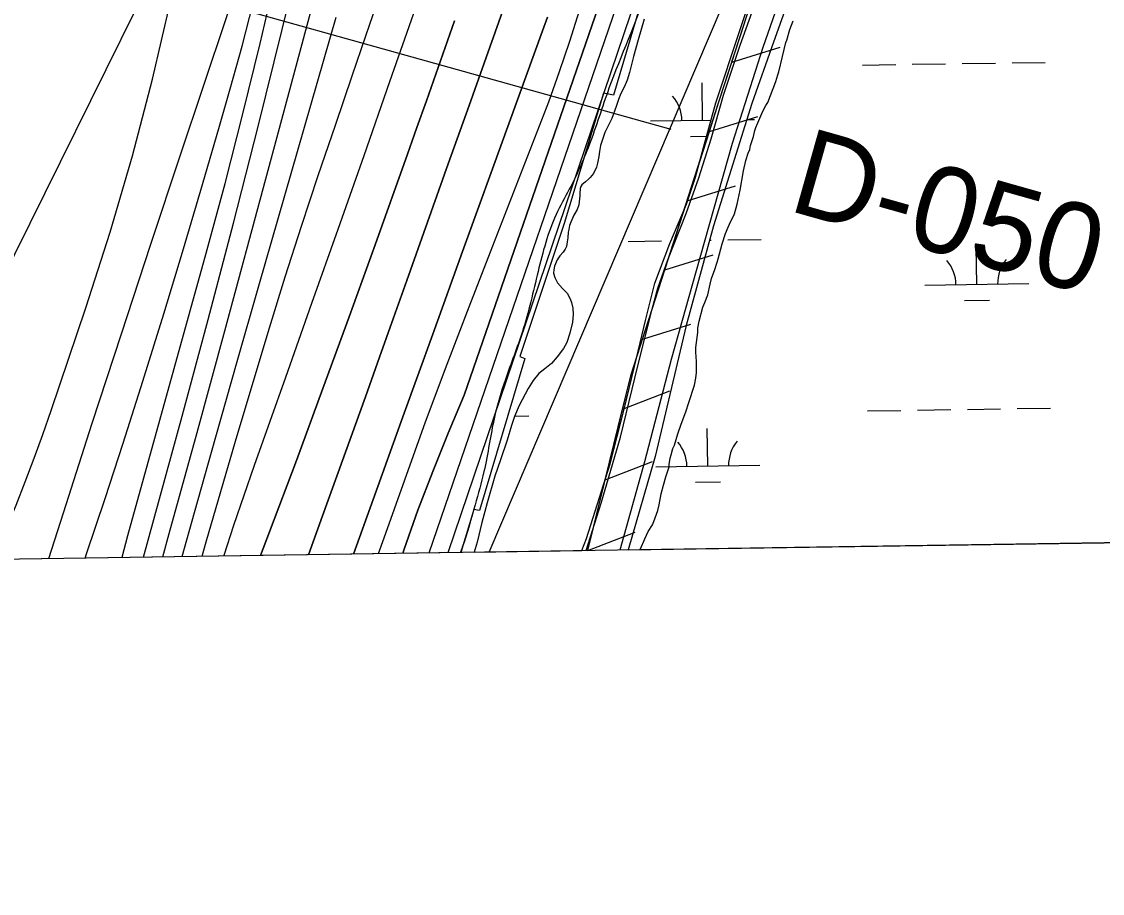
# Model space of a CAD drawing. Extents: x 3807117 to 3845308, y 337856 to 363736.
# Drawn here: x 3832831 to 3833871, y 343281 to 344120 of the extents above; entities that cross this region are included whole.
import ezdxf

# ---------------------------------------------------------------- set-up
doc = ezdxf.new("R2010")
doc.units = 0
for name, color, linetype in [('V-GRID-FRAM', 7, 'Continuous'), ('V-LEVE-TOET', 7, 'Continuous'), ('V-RIVR-EDGE', 7, 'Continuous'), ('V-RIVR-RANG', 7, 'Continuous'), ('V-RIVR-RANG-IDEN', 7, 'Continuous'), ('V-RRAP-FSHR', 7, 'Continuous'), ('V-RRAP-RVMT', 7, 'Continuous'), ('V-SITE-VEGE', 7, 'Continuous'), ('V-TOPO-DPTH', 7, 'Continuous'), ('V-TOPO-MAJR', 7, 'Continuous'), ('V-TOPO-MINR', 7, 'Continuous'), ('V-TOPO-WATR', 7, 'Continuous'), ('V-WETL-SWMP', 7, 'Continuous')]:
    doc.layers.add(name, color=color, linetype=linetype)

msp = doc.modelspace()

# ---------------------------------------------------------------- linework, layer by layer
at = {"layer": 'V-GRID-FRAM'}
msp.add_lwpolyline([(3811100.6, 361461.9), (3842914.2, 361938.5), (3843194.5, 343758.3), (3811365, 343281.4), (3811100.6, 361461.9)], dxfattribs=at)
at = {"layer": 'V-LEVE-TOET'}
for points in [[(3833737, 344568.4), (3833722.6, 344552.6), (3833711.9, 344536.3), (3833699.7, 344512.1), (3833685.8, 344483), (3833672.9, 344455.1), (3833643.7, 344371.5), (3833609.1, 344278.3), (3833577.2, 344188.9), (3833544.5, 344094.9), (3833514.8, 344002.7), (3833483.7, 343892.8), (3833456.2, 343794.9), (3833430.6, 343696.6), (3833406.6, 343611.6)], [(3833374.2, 343611.1), (3833388.8, 343656.6), (3833407.5, 343720.1), (3833424.1, 343788.7), (3833437.8, 343843.2), (3833443.3, 343863.4), (3833452.9, 343890.8), (3833470.5, 343935.2), (3833482.8, 343969.6), (3833494.5, 344007), (3833506.5, 344049), (3833522.7, 344097.2), (3833549.9, 344173.1)]]:
    msp.add_lwpolyline(points, dxfattribs=at)
at = {"layer": 'V-RIVR-EDGE'}
msp.add_spline([(3833993.6, 346073.1), (3834014.8, 346049.1), (3834027.9, 346045), (3834044.2, 346044.5), (3834056.4, 346046.8), (3834063.2, 346046.7), (3834065.5, 346045.4), (3834066.8, 346025), (3834070.8, 346004.7), (3834083.3, 345964.4), (3834083.8, 345960.8), (3834080.2, 345959.9), (3834071.6, 345964), (3834066.6, 345963.1), (3834057.1, 345958.1), (3834056.2, 345945.9), (3834053.9, 345939.6), (3834045.3, 345936), (3834032.2, 345933.8), (3834020.9, 345934.3), (3834010.5, 345930.7), (3833991.4, 345919.4), (3833968.3, 345903.6), (3833937.1, 345880.2), (3833918, 345855.8), (3833899.9, 345825.6), (3833887.6, 345788.5), (3833879.4, 345756.5), (3833874.3, 345710.4), (3833869.2, 345675.1), (3833852.3, 345618.6), (3833845.5, 345588.3), (3833842.7, 345557.2), (3833837.6, 345515.1), (3833834.3, 345463.1), (3833833.3, 345422.9), (3833835.5, 345389.9), (3833826.7, 345327.5), (3833812.6, 345266), (3833811.6, 345236.2), (3833805.6, 345198.2), (3833800.1, 345162.1), (3833798.7, 345131.8), (3833801.8, 345114.6), (3833810.8, 345092.4), (3833826.6, 345068.4), (3833838.7, 345048.9), (3833853.2, 345041.2), (3833864.5, 345032.1), (3833872.1, 345019.5), (3833872.1, 345008.2), (3833866.1, 344947.6), (3833859.1, 344872.5), (3833858.2, 344868), (3833853.6, 344868), (3833833.3, 344878), (3833815.7, 344894.8), (3833804.9, 344906.1), (3833797.7, 344908.9), (3833783.2, 344908.5), (3833736.6, 344893.2), (3833706.2, 344865.7), (3833687.6, 344845.4), (3833676.3, 344827.3), (3833665.4, 344800.7), (3833650.8, 344767.7), (3833632.6, 344715.8), (3833615.3, 344663.8), (3833598.9, 344623.1), (3833579.4, 344582.5), (3833566.6, 344539.6), (3833556.6, 344505.7), (3833525.6, 344416.7), (3833510.6, 344373.8), (3833496, 344333.1), (3833486.9, 344308.7), (3833473.3, 344271.2), (3833455.1, 344226.1), (3833441.8, 344180.9), (3833432.7, 344150.1), (3833396.3, 344055.7), (3833377.2, 344001.1), (3833358.1, 343958.6), (3833345.4, 343934.2), (3833328.1, 343879.6), (3833313, 343821.7), (3833296.6, 343775.6), (3833286.1, 343739.5), (3833276, 343687.1), (3833267.4, 343655), (3833255.1, 343614.3), (3833253.2, 343609.3)], degree=3, dxfattribs=at)
at = {"layer": 'V-RIVR-RANG'}
msp.add_line((3833456, 344016), (3832602.7, 344254.8), dxfattribs=at)
at = {"layer": 'V-RRAP-FSHR'}
for p, q in [((3833514.5, 344080.9), (3833561.1, 344095.2)), ((3833492.9, 344014.3), (3833539.6, 344028.6)), ((3833471.4, 343947.6), (3833518.1, 343962)), ((3833449.9, 343881), (3833496.6, 343895.4)), ((3833428.5, 343814.4), (3833475.1, 343828.8)), ((3833409.3, 343747.1), (3833454.8, 343764.8)), ((3833392.6, 343679.1), (3833438.1, 343696.8)), ((3833375.9, 343611.2), (3833421.4, 343628.8))]:
    msp.add_line(p, q, dxfattribs=at)
for points in [[(3833514.5, 344080.9), (3833536, 344147.5)], [(3833375.9, 343611.2), (3833417.5, 343780.5), (3833502.1, 344042.6), (3833526.9, 344119.2)], [(3833492.9, 344014.3), (3833502.1, 344042.6), (3833514.5, 344080.9)], [(3833449.9, 343881), (3833471.4, 343947.6), (3833492.9, 344014.3)], [(3833428.5, 343814.4), (3833449.9, 343881)], [(3833409.3, 343747.1), (3833417.5, 343780.5), (3833428.5, 343814.4)], [(3833392.6, 343679.1), (3833409.3, 343747.1)], [(3833375.9, 343611.2), (3833392.6, 343679.1)]]:
    msp.add_lwpolyline(points, dxfattribs=at)
at = {"layer": 'V-RRAP-RVMT'}
for p, q in [((3833439.8, 344181.1), (3833400.6, 344049.1)), ((3833391.1, 344051.2), (3833353.2, 343925.8)), ((3833400.6, 344049.1), (3833391.1, 344051.2)), ((3833353.2, 343925.8), (3833310.5, 343797.7)), ((3833315.2, 343795.7), (3833271.7, 343649.7)), ((3833310.5, 343797.7), (3833315.2, 343795.7)), ((3833266.4, 343650.6), (3833253.6, 343609.3)), ((3833271.7, 343649.7), (3833266.4, 343650.6)), ((3833253.6, 343609.3), (3832567.7, 343599.1))]:
    msp.add_line(p, q, dxfattribs=at)
at = {"layer": 'V-SITE-VEGE'}
for p, q in [((3833570.2, 344112.2), (3833573.4, 344120.5)), ((3833567.5, 344102), (3833570.2, 344112.2)), ((3833563.3, 344086.4), (3833566.5, 344099.7)), ((3833566.5, 344099.7), (3833567.5, 344102)), ((3833559.7, 344071.6), (3833563.3, 344086.4)), ((3833556.9, 344062.4), (3833558.8, 344068.8)), ((3833558.8, 344068.8), (3833559.7, 344071.6)), ((3833549.1, 344042.1), (3833556.9, 344062.4)), ((3833537.6, 344018.1), (3833544.5, 344033.8)), ((3833544.5, 344033.8), (3833547.3, 344039.3)), ((3833547.3, 344039.3), (3833549.1, 344042.1)), ((3833535.3, 344009.4), (3833536.7, 344015.3)), ((3833536.7, 344015.3), (3833537.6, 344018.1)), ((3833532.6, 344000.6), (3833535.3, 344009.4)), ((3833528, 343986.3), (3833530.3, 343993.2)), ((3833530.3, 343993.2), (3833531.7, 343996.9)), ((3833531.7, 343996.9), (3833532.6, 344000.6)), ((3833525.7, 343976.2), (3833528, 343986.3)), ((3833522.5, 343957.7), (3833525.7, 343976.2)), ((3833519.8, 343944.3), (3833522.5, 343957.7)), ((3833517, 343935.1), (3833519.8, 343944.3)), ((3833512.4, 343925), (3833517, 343935.1)), ((3833508.3, 343916.2), (3833511, 343922.2)), ((3833511, 343922.2), (3833512.4, 343925)), ((3833505.1, 343906.1), (3833508.3, 343916.2)), ((3833501.4, 343891.8), (3833505.1, 343906.1)), ((3833498.2, 343881.6), (3833500.5, 343888.5)), ((3833500.5, 343888.5), (3833501.4, 343891.8)), ((3833495, 343872.9), (3833498.2, 343881.6)), ((3833491.3, 343857.2), (3833493.6, 343867.3)), ((3833493.6, 343867.3), (3833495, 343872.9)), ((3833488.6, 343849.8), (3833491.3, 343857.2)), ((3833483.1, 343831.8), (3833486.7, 343845.2)), ((3833486.7, 343845.2), (3833488.6, 343849.8)), ((3833481.7, 343824.9), (3833483.1, 343831.8)), ((3833481.7, 343820.8), (3833481.7, 343824.9)), ((3833479.9, 343806.5), (3833481.7, 343820.8)), ((3833479.9, 343801.9), (3833479.9, 343806.5)), ((3833480.4, 343793.1), (3833479.9, 343801.9)), ((3833480.4, 343782.5), (3833480.4, 343793.1)), ((3833479.9, 343777), (3833480.4, 343782.5)), ((3833478.6, 343770.1), (3833479.9, 343777)), ((3833473, 343753.5), (3833478.6, 343770.1)), ((3833470.3, 343744.7), (3833473, 343753.5)), ((3833465.7, 343732.7), (3833470.3, 343744.7)), ((3833462.5, 343723.5), (3833465.7, 343732.7)), ((3833459.3, 343712.4), (3833462.5, 343723.5)), ((3833457.9, 343709.2), (3833459.3, 343712.4)), ((3833454.2, 343694), (3833455.2, 343700)), ((3833455.2, 343700), (3833456.1, 343703.2)), ((3833456.1, 343703.2), (3833457.9, 343709.2)), ((3833451, 343682), (3833454.2, 343691.7)), ((3833454.2, 343691.7), (3833454.2, 343694)), ((3833448.7, 343674.1), (3833451, 343682)), ((3833446.4, 343665.8), (3833448.7, 343674.1)), ((3833444.6, 343655.2), (3833445.1, 343658.5)), ((3833445.1, 343658.5), (3833446.4, 343665.8)), ((3833439.6, 343639.1), (3833443.2, 343649.7)), ((3833443.2, 343649.7), (3833444.6, 343655.2)), ((3833438.2, 343635.9), (3833439.6, 343639.1)), ((3833430.8, 343622.5), (3833434.1, 343629.4)), ((3833434.1, 343629.4), (3833438.2, 343635.9)), ((3834258.8, 343624.4), (3833426.5, 343611.9)), ((3833426.7, 343612.8), (3833430.8, 343622.5)), ((3833426.5, 343611.9), (3833426.7, 343612.8))]:
    msp.add_line(p, q, dxfattribs=at)
at = {"layer": 'V-TOPO-DPTH'}
for points in [[(3833197.9, 343608.5), (3833199.3, 343612.5), (3833212.5, 343649.9), (3833226.7, 343687.1), (3833241.5, 343724), (3833256.9, 343760.7), (3833412.9, 344211.6), (3833418.8, 344231.9), (3833424.8, 344252.2), (3833431, 344272.4), (3833437.4, 344292.6), (3833461.5, 344368.3), (3833463.6, 344374), (3833465.9, 344379.6), (3833468.6, 344385.1), (3833471.5, 344390.5), (3833474.9, 344395.5), (3833657.1, 344889.9)], [(3833657.1, 344889.9), (3833474.9, 344395.5), (3833471.5, 344390.5), (3833468.6, 344385.1), (3833465.9, 344379.6), (3833463.6, 344374), (3833461.5, 344368.3), (3833437.4, 344292.6), (3833431, 344272.4), (3833424.8, 344252.2), (3833418.8, 344231.9), (3833412.9, 344211.6), (3833256.9, 343760.7), (3833241.5, 343724), (3833226.7, 343687.1), (3833212.5, 343649.9), (3833199.3, 343612.5), (3833197.9, 343608.5)], [(3833241.7, 343609.2), (3833454.7, 344238.2), (3833455.9, 344242.7), (3833457.2, 344247.2), (3833458.5, 344251.6), (3833459.8, 344256.1), (3833465.2, 344274.2), (3833465.7, 344275.4), (3833466.2, 344276.6), (3833466.8, 344277.8), (3833467.4, 344279), (3833468.2, 344280), (3833469.1, 344280.9), (3833470.2, 344281.6), (3833471.3, 344282.2), (3833688.8, 344887.2)], [(3833333.2, 344240.8), (3833281.5, 344095.4), (3833261.6, 344039.3), (3833241.7, 343983.2), (3833221.8, 343927.1), (3833201.9, 343871), (3833189.1, 343835.1), (3833175.6, 343797), (3833162, 343758.9), (3833148.3, 343720.8), (3833134.5, 343682.7), (3833120.7, 343644.6), (3833107.1, 343607.1)], [(3833107.1, 343607.1), (3833120.7, 343644.6), (3833134.5, 343682.7), (3833148.3, 343720.8), (3833162, 343758.9), (3833175.6, 343797), (3833189.1, 343835.1), (3833201.9, 343871), (3833221.8, 343927.1), (3833241.7, 343983.2), (3833261.6, 344039.3), (3833281.5, 344095.4), (3833333.2, 344240.8)], [(3833247.7, 344120.6), (3833238.7, 344095), (3833229.7, 344069.3), (3833220.6, 344043.7), (3833211.5, 344018.1), (3833202.4, 343992.5), (3833171.2, 343905.2), (3833146.2, 343836), (3833121, 343766.9), (3833095.5, 343697.9), (3833069.6, 343629), (3833061.1, 343606.5)], [(3833061.1, 343606.5), (3833069.6, 343629), (3833095.5, 343697.9), (3833121, 343766.9), (3833146.2, 343836), (3833171.2, 343905.2), (3833202.4, 343992.5), (3833211.5, 344018.1), (3833220.6, 344043.7), (3833229.7, 344069.3), (3833238.7, 344095), (3833247.7, 344120.6)], [(3833337.2, 344124.2), (3833332.4, 344111.1), (3833284.3, 343978.3), (3833255.4, 343898.8), (3833226.7, 343819.3), (3833198, 343739.7), (3833169.3, 343660.1), (3833150.5, 343607.8)], [(3833150.5, 343607.8), (3833169.3, 343660.1), (3833198, 343739.7), (3833226.7, 343819.3), (3833255.4, 343898.8), (3833284.3, 343978.3), (3833332.4, 344111.1), (3833337.2, 344124.2)]]:
    msp.add_lwpolyline(points, dxfattribs=at)
at = {"layer": 'V-TOPO-MAJR'}
for points in [[(3832927.6, 343604.5), (3832927.7, 343604.8), (3832933.4, 343625.5), (3833008.7, 343897), (3833026.8, 343964.1), (3833044.1, 344031.3), (3833060.5, 344098.8), (3833076.3, 344166.5), (3833098.8, 344266.9), (3833102.7, 344284.5), (3833106.3, 344302.2), (3833109.8, 344319.9), (3833113.1, 344337.6), (3833315.5, 344933.2)], [(3833025.8, 343605.9), (3833026, 343606.6), (3833035.4, 343635.6), (3833045.1, 343664.5), (3833055.2, 343693.3), (3833085.2, 343777.9), (3833110.4, 343849), (3833135.6, 343920.1), (3833160.6, 343991.2), (3833185.5, 344062.3), (3833258.4, 344270.6)]]:
    msp.add_lwpolyline(points, dxfattribs=at)
at = {"layer": 'V-TOPO-MINR'}
for points in [[(3833281.1, 343609.7), (3833542.8, 344222.6), (3833545, 344227.5), (3833547.8, 344232), (3833575.6, 344292.3), (3833849.9, 345478.8)], [(3832857.2, 343603.4), (3832871.3, 343647.4), (3832899.1, 343733.6), (3832927.1, 343819.7), (3832955.4, 343905.8), (3832984, 343991.7), (3833028.1, 344123.8), (3833034.6, 344143.7), (3833041, 344163.6), (3833047.2, 344183.6), (3833053.3, 344203.7), (3833056.1, 344213.1), (3833060.5, 344228.5), (3833064.5, 344244), (3833068.1, 344259.6), (3833071.4, 344275.3), (3833076.3, 344300.2), (3833076.9, 344303.5), (3833077.5, 344306.7), (3833078, 344310), (3833078.5, 344313.2), (3833399.1, 345475.9)], [(3832802.8, 343602.6), (3832806.4, 343610), (3832816.3, 343632.2), (3832825.7, 343654.7), (3832834.5, 343677.3), (3832843.1, 343700), (3832851.4, 343722.9), (3832859.4, 343745.9), (3832892.9, 343844.7), (3832916.2, 343917.4), (3832937.8, 343990.7), (3832956.9, 344064.6), (3832974.3, 344139), (3833004.1, 344276.9), (3833007.8, 344296.9), (3833383.2, 345461.1)], [(3832892.2, 343603.9), (3832893.6, 343607.9), (3832911.4, 343661.1), (3832928.7, 343714.4), (3832945.8, 343767.9), (3832949.4, 343779.3), (3832967.8, 343838.7), (3832985.9, 343898.1), (3833003.6, 343957.6), (3833021, 344017.2), (3833031.9, 344055.2), (3833043.3, 344096.4), (3833054, 344137.7), (3833063.8, 344179.3), (3833073, 344221), (3833086.5, 344285.4), (3833088.4, 344295), (3833090.3, 344304.7), (3833092, 344314.4), (3833093.6, 344324.1), (3833468.2, 345464.2)], [(3832948.4, 343604.8), (3832985.5, 343740.4), (3833010.5, 343833.2), (3833034.9, 343926), (3833058.6, 344019.1), (3833081.7, 344112.3), (3833113.8, 344243.7), (3833120.3, 344271.3), (3833126.7, 344299), (3833132.8, 344326.8), (3833138.6, 344354.6), (3833348, 344895.8)], [(3833197.9, 343608.5), (3833199.3, 343612.5), (3833212.5, 343649.9), (3833226.7, 343687.1), (3833241.5, 343724), (3833256.9, 343760.7), (3833412.9, 344211.6), (3833418.8, 344231.9), (3833424.8, 344252.2), (3833431, 344272.4), (3833437.4, 344292.6), (3833461.5, 344368.3), (3833463.6, 344374), (3833465.9, 344379.6), (3833468.6, 344385.1), (3833471.5, 344390.5), (3833474.9, 344395.5), (3833657.1, 344889.9)], [(3833223.3, 343608.9), (3833434.6, 344225.3), (3833438, 344237.5), (3833441.5, 344249.6), (3833445.1, 344261.7), (3833448.8, 344273.8), (3833463.5, 344321.3), (3833464.7, 344324.8), (3833466.1, 344328.1), (3833467.7, 344331.4), (3833469.4, 344334.6), (3833471.5, 344337.5), (3833473.9, 344340.2), (3833668.7, 344873.7)], [(3832967, 343605), (3832973.1, 343627.4), (3832999.9, 343724.8), (3833026.5, 343822.3), (3833052.9, 343919.8), (3833079.2, 344017.3), (3833144.9, 344262.2)], [(3833107.1, 343607.1), (3833120.7, 343644.6), (3833134.5, 343682.7), (3833148.3, 343720.8), (3833162, 343758.9), (3833175.6, 343797), (3833189.1, 343835.1), (3833201.9, 343871), (3833221.8, 343927.1), (3833241.7, 343983.2), (3833261.6, 344039.3), (3833281.5, 344095.4), (3833333.2, 344240.8)], [(3833004.8, 343605.6), (3833008.7, 343619.6), (3833022.8, 343668), (3833037, 343716.4), (3833054.7, 343776.3), (3833069.6, 343825.3), (3833084.8, 343874.3), (3833100.5, 343923.1), (3833116.6, 343971.7), (3833133.1, 344020.3), (3833149.5, 344068.8), (3833166.1, 344117.3), (3833182.8, 344165.8)], [(3832678, 343600.7), (3832941.6, 344132.9)], [(3833174.6, 343608.2), (3833179.9, 343623.5), (3833199.7, 343679.3), (3833219.8, 343735), (3833240.6, 343790.4), (3833261.8, 343845.7), (3833282.2, 343898.4), (3833293.5, 343927.3), (3833304.7, 343956.1), (3833316, 343984.9), (3833327.3, 344013.8), (3833338.3, 344042.7), (3833348.8, 344071.8), (3833358.6, 344101.2), (3833368, 344130.7)], [(3832985.7, 343605.3), (3832997.5, 343647.6), (3833017.9, 343720.4), (3833038.5, 343793.1), (3833059.3, 343865.7), (3833128.3, 344105.3), (3833133.8, 344124.1)], [(3833061.1, 343606.5), (3833069.6, 343629), (3833095.5, 343697.9), (3833121, 343766.9), (3833146.2, 343836), (3833171.2, 343905.2), (3833202.4, 343992.5), (3833211.5, 344018.1), (3833220.6, 344043.7), (3833229.7, 344069.3), (3833238.7, 344095), (3833247.7, 344120.6)], [(3833150.5, 343607.8), (3833169.3, 343660.1), (3833198, 343739.7), (3833226.7, 343819.3), (3833255.4, 343898.8), (3833284.3, 343978.3), (3833332.4, 344111.1), (3833337.2, 344124.2)]]:
    msp.add_lwpolyline(points, dxfattribs=at)
at = {"layer": 'V-TOPO-WATR'}
msp.add_lwpolyline([(3833241.7, 343609.2), (3833454.7, 344238.2), (3833455.9, 344242.7), (3833457.2, 344247.2), (3833458.5, 344251.6), (3833459.8, 344256.1), (3833465.2, 344274.2), (3833465.7, 344275.4), (3833466.2, 344276.6), (3833466.8, 344277.8), (3833467.4, 344279), (3833468.2, 344280), (3833469.1, 344280.9), (3833470.2, 344281.6), (3833471.3, 344282.2), (3833688.8, 344887.2)], dxfattribs=at)
at = {"layer": 'V-WETL-SWMP'}
for p, q in [((3833593.7, 344210.1), (3833554.7, 344100.1)), ((3833521.9, 344110.4), (3833548.6, 344191.4)), ((3833430, 344122.1), (3833424.4, 344102.4)), ((3833499.1, 344041.6), (3833521.9, 344110.4)), ((3833424.4, 344102.4), (3833420, 344086.2)), ((3833554.7, 344100.1), (3833533.8, 344041.2)), ((3833420, 344086.2), (3833418.1, 344078.7)), ((3833418.1, 344078.7), (3833416.1, 344071)), ((3833640.2, 344078.1), (3833672.2, 344078.6)), ((3833688.2, 344078.8), (3833720.2, 344079.3)), ((3833736.2, 344079.5), (3833768.2, 344080)), ((3833784.2, 344080.3), (3833816.2, 344080.7)), ((3833413.8, 344063.5), (3833410.9, 344056.8)), ((3833416.1, 344071), (3833413.8, 344063.5)), ((3833410.9, 344056.8), (3833407.7, 344050.6)), ((3833486.4, 344025), (3833485.9, 344061)), ((3833405.5, 344044.9), (3833403.3, 344038.1)), ((3833407.7, 344050.6), (3833405.5, 344044.9)), ((3833403.3, 344038.1), (3833399, 344026.8)), ((3833488.1, 344002.4), (3833499.1, 344041.6)), ((3833533.8, 344041.2), (3833496.9, 343923.4)), ((3833399, 344026.8), (3833392.4, 344013.1)), ((3833436.4, 344024.3), (3833494.5, 344025.2)), ((3833529, 344025.7), (3833536.4, 344025.8)), ((3833392.4, 344013.1), (3833389.6, 344005.6)), ((3833388.1, 344000.8), (3833387.1, 343995.1)), ((3833389.6, 344005.6), (3833388.1, 344000.8)), ((3833474.6, 344009.4), (3833490.1, 344009.7)), ((3833479.4, 343970.4), (3833488.1, 344002.4)), ((3833387.1, 343995.1), (3833386.4, 343990.2)), ((3833385.3, 343983.8), (3833384.3, 343979.9)), ((3833386.4, 343990.2), (3833385.3, 343983.8)), ((3833378.3, 343969.9), (3833376.7, 343968.3)), ((3833381.5, 343973.9), (3833378.3, 343969.9)), ((3833384.3, 343979.9), (3833381.5, 343973.9)), ((3833470.8, 343944.3), (3833479.4, 343970.4)), ((3833368.5, 343959.2), (3833368.2, 343954.4)), ((3833369.1, 343961.3), (3833368.5, 343959.2)), ((3833370.2, 343962.8), (3833369.1, 343961.3)), ((3833373.6, 343965.7), (3833370.2, 343962.8)), ((3833376.7, 343968.3), (3833373.6, 343965.7)), ((3833368.1, 343952.2), (3833367.2, 343943.7)), ((3833368.2, 343954.4), (3833368.1, 343952.2)), ((3833365.6, 343939.2), (3833363.5, 343935.2)), ((3833367.2, 343943.7), (3833365.6, 343939.2)), ((3833455, 343906.3), (3833470.8, 343944.3)), ((3833362.6, 343933.6), (3833359.7, 343927)), ((3833363.5, 343935.2), (3833362.6, 343933.6)), ((3833357.6, 343920), (3833357.1, 343917.2)), ((3833358.4, 343923.9), (3833357.6, 343920)), ((3833359.7, 343927), (3833358.4, 343923.9)), ((3833496.9, 343923.4), (3833470.5, 343827.7)), ((3833356.2, 343908), (3833355.3, 343903.5)), ((3833356.6, 343911.8), (3833356.2, 343908)), ((3833357.1, 343917.2), (3833356.6, 343911.8)), ((3833414.7, 343908.5), (3833446.7, 343909)), ((3833493.1, 343909.7), (3833494.7, 343909.7)), ((3833510.7, 343910), (3833542.7, 343910.4)), ((3833352.1, 343898.1), (3833349, 343894.7)), ((3833354.1, 343900.9), (3833352.1, 343898.1)), ((3833355.3, 343903.5), (3833354.1, 343900.9)), ((3833440.4, 343868.4), (3833455, 343906.3)), ((3833750.2, 343867.1), (3833749.7, 343903.1)), ((3833346.4, 343890.9), (3833344, 343884.8)), ((3833349, 343894.7), (3833346.4, 343890.9)), ((3833343.1, 343881), (3833342.9, 343877.9)), ((3833342.9, 343877.9), (3833344.2, 343873.8)), ((3833344, 343884.8), (3833343.1, 343881)), ((3833344.2, 343873.8), (3833346.9, 343868.5)), ((3833346.9, 343868.5), (3833351.5, 343863.3)), ((3833431.8, 343833.6), (3833440.4, 343868.4)), ((3833700.2, 343866.4), (3833800.2, 343867.9)), ((3833351.5, 343863.3), (3833356, 343858.7)), ((3833356, 343858.7), (3833359, 343853.3)), ((3833359, 343853.3), (3833360.2, 343849.6)), ((3833360.2, 343849.6), (3833361.4, 343844.4)), ((3833738.5, 343851.5), (3833762.5, 343851.9)), ((3833361.7, 343838.2), (3833361.1, 343830.9)), ((3833361.4, 343844.4), (3833361.7, 343838.2)), ((3833361.1, 343830.9), (3833358.7, 343820.1)), ((3833420.8, 343788.1), (3833431.8, 343833.6)), ((3833470.5, 343827.7), (3833440.7, 343701.6)), ((3833358.7, 343820.1), (3833355.6, 343811.1)), ((3833352.4, 343805.5), (3833346.5, 343797.3)), ((3833355.6, 343811.1), (3833352.4, 343805.5)), ((3833346.5, 343797.3), (3833340.9, 343791.1)), ((3833334.5, 343785.9), (3833328.9, 343781.4)), ((3833340.9, 343791.1), (3833334.5, 343785.9)), ((3833411, 343747), (3833420.8, 343788.1)), ((3833323.2, 343774.7), (3833318.6, 343767.1)), ((3833328.9, 343781.4), (3833323.2, 343774.7)), ((3833318.6, 343767.1), (3833309.8, 343750.6)), ((3833309.8, 343750.6), (3833305.4, 343740.1)), ((3833397.6, 343694.4), (3833411, 343747)), ((3833645.2, 343745.5), (3833677.2, 343745.9)), ((3833693.2, 343746.2), (3833725.2, 343746.7)), ((3833741.2, 343746.9), (3833773.2, 343747.4)), ((3833789.2, 343747.6), (3833821.2, 343748.1)), ((3833302.4, 343731.3), (3833298.4, 343717.3)), ((3833305.4, 343740.1), (3833302.4, 343731.3)), ((3833305.5, 343740.4), (3833319.3, 343740.6)), ((3833491.4, 343692.4), (3833490.8, 343728.4)), ((3833298.4, 343717.3), (3833291.9, 343698.5)), ((3833440.7, 343701.6), (3833414.8, 343611.8)), ((3833291.9, 343698.5), (3833286.5, 343682.7)), ((3833374.8, 343622.8), (3833397.6, 343694.4)), ((3833441.4, 343691.7), (3833541.4, 343693.2)), ((3833286.5, 343682.7), (3833279.2, 343657.1)), ((3833479.6, 343676.8), (3833503.6, 343677.2)), ((3833276.9, 343648.8), (3833274, 343638.1)), ((3833279.2, 343657.1), (3833276.9, 343648.8)), ((3833274, 343638.1), (3833269.5, 343619.2)), ((3833414.8, 343611.8), (3835523.3, 343643.3)), ((3833269.5, 343619.2), (3833266.5, 343609.5)), ((3833370.3, 343611.1), (3833374.8, 343622.8)), ((3833266.5, 343609.5), (3833370.3, 343611.1))]:
    msp.add_line(p, q, dxfattribs=at)
for centre, start, end in [((3833431.2, 344024.7), 0.0865, 41.6302), ((3833695, 343866.8), 0.0865, 41.6302), ((3833805.5, 343868.4), 140.0865, 181.6302), ((3833436.1, 343692.1), 0.0865, 41.6302), ((3833546.6, 343693.7), 140.0865, 181.6302)]:
    msp.add_arc(centre, 35.2, start, end, dxfattribs=at)

# ---------------------------------------------------------------- texts
at = {"layer": 'V-RIVR-RANG-IDEN'}
msp.add_text('D-050', height=83, rotation=344.2253, dxfattribs=at).set_placement((3833567, 343938.7))

doc.saveas('drawing.dxf')
